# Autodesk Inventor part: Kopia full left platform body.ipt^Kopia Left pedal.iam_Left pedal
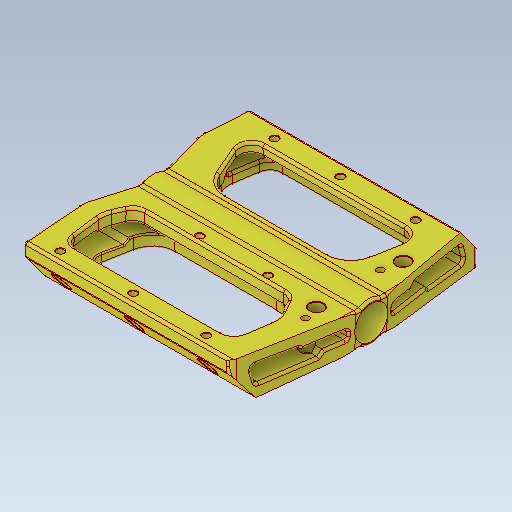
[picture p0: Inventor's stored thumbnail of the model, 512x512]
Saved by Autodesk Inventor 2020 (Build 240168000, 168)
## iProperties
Created: 2017-10
Part Number: Kopia full left platform body.ipt^Kopia Left pedal.iam_Left pedal
Material: solidworks materials|7075-T6 (SN)|177
Document SubType Name: Modeling
Designer: Tomasz
Density: 2.81 g/cm^3
Appearance: 221,232,255
Sending System: SolidWorks 2017
Last Author: Tomasz
Last Saved: 2017-11-19
Author: Tomasz
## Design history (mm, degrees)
feature "full left platform body.ipt"
node "Bryła1"
